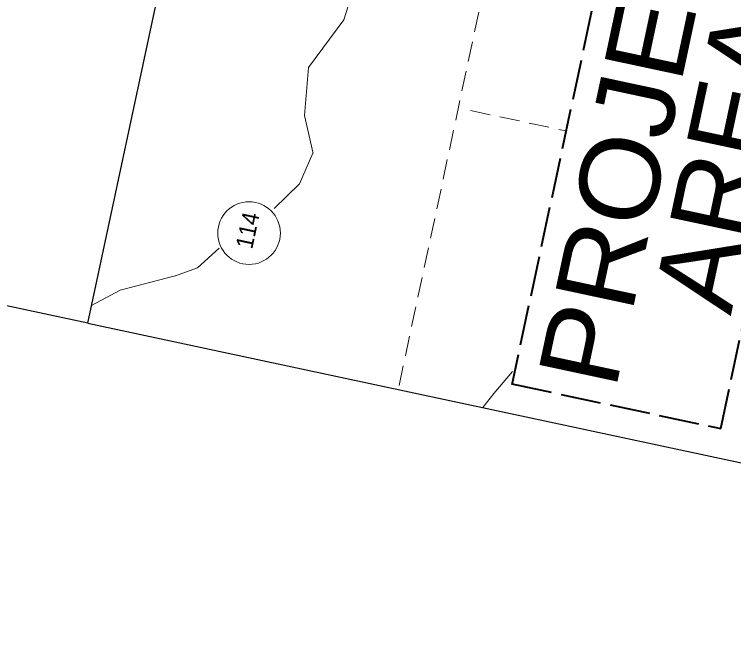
# Model space of a CAD drawing. Extents: x 2363411 to 2369126, y 6976878 to 6988319.
# Drawn here: x 2365656.3 to 2365871.2, y 6976877.7 to 6977067.2 of the extents above; entities that cross this region are included whole.
import ezdxf

# ---------------------------------------------------------------- set-up
doc = ezdxf.new("R2010")
doc.units = 0
doc.header["$LTSCALE"] = 2
doc.linetypes.add('LONG_DASHED', pattern=[7.5, 6, -1.5])
doc.linetypes.add('MEDIUM_DASHED', pattern=[4.5, 3, -1.5])
doc.layers.add('62', color=7, linetype='Continuous', lineweight=13)
doc.layers.add('63', color=7, linetype='Continuous', lineweight=13)

msp = doc.modelspace()

# ---------------------------------------------------------------- linework, layer by layer
at = {"layer": '62', "lineweight": 25}
msp.add_line((2365678.211, 6976974.92), (2365772.152, 6977414.588), dxfattribs=at)
at = {"layer": '62', "linetype": 'MEDIUM_DASHED'}
for p, q in [((2365864.629, 6977393.47), (2365770.962, 6976955.102)), ((2365792.552, 6977038.481), (2365821.113, 6977032.378))]:
    msp.add_line(p, q, dxfattribs=at)
at = {"layer": '62'}
for p, q in [((2365745.482, 6977025.71), (2365741.426, 6977016.523)), ((2365741.426, 6977016.523), (2365733.932, 6977009.242)), ((2365710.989, 6976991.456), (2365717.459, 6976997.299)), ((2365704.102, 6976988.947), (2365710.989, 6976991.456)), ((2365799.574, 6976953.962), (2365805.114, 6976960.509)), ((2365796.248, 6976949.699), (2365799.574, 6976953.962))]:
    msp.add_line(p, q, dxfattribs=at)
at = {"layer": '62', "lineweight": 25}
for points in [[(2365678.211, 6976974.92), (2365561.054, 6976999.954), (2365654.924, 6977439.292), (2365772.152, 6977414.588)], [(2365678.211, 6976974.92), (2366133.213, 6976877.7), (2366227.156, 6977317.368), (2365772.152, 6977414.588)]]:
    msp.add_lwpolyline(points, dxfattribs=at)
at = {"layer": '62'}
for points in [[(2365745.602, 6977025.615), (2365742.995, 6977037.011), (2365744.177, 6977051.369), (2365754.758, 6977065.562), (2365757.967, 6977076.059), (2365767.656, 6977087.91), (2365774.215, 6977096.102), (2365778.852, 6977103.376), (2365783.338, 6977114.034), (2365786.122, 6977122.873), (2365789.101, 6977134.663), (2365791.544, 6977148.682), (2365797.575, 6977165.918), (2365800.831, 6977177.279), (2365805.2, 6977190.083), (2365814.728, 6977203.211), (2365824.115, 6977215.605), (2365833.318, 6977226.804), (2365847.376, 6977238.756), (2365856.409, 6977246.882), (2365866.274, 6977257.086), (2365874.425, 6977262.384)], [(2365679.344, 6976980.224), (2365687.88, 6976984.754), (2365704.316, 6976989.086)]]:
    msp.add_lwpolyline(points, dxfattribs=at)
at = {"layer": '62', "linetype": 'LONG_DASHED', "lineweight": 40}
msp.add_lwpolyline([(2365804.964, 6976956.79), (2365867.37, 6976943.454), (2365903.697, 6977113.468), (2365841.291, 6977126.802), (2365804.897, 6976956.481)], dxfattribs=at)
at = {"layer": '62'}
msp.add_circle((2365726.392, 6977001.845), 9.364, dxfattribs=at)
at = {"layer": '63', "lineweight": 25}
msp.add_line((2365678.211, 6976974.92), (2365772.152, 6977414.588), dxfattribs=at)
at = {"layer": '63', "linetype": 'MEDIUM_DASHED'}
for p, q in [((2365864.629, 6977393.47), (2365770.962, 6976955.102)), ((2365792.552, 6977038.481), (2365821.113, 6977032.378))]:
    msp.add_line(p, q, dxfattribs=at)
at = {"layer": '63'}
for p, q in [((2365745.482, 6977025.71), (2365741.426, 6977016.523)), ((2365741.426, 6977016.523), (2365733.932, 6977009.242)), ((2365710.989, 6976991.456), (2365717.459, 6976997.299)), ((2365704.102, 6976988.947), (2365710.989, 6976991.456)), ((2365799.574, 6976953.962), (2365805.114, 6976960.509)), ((2365796.248, 6976949.699), (2365799.574, 6976953.962))]:
    msp.add_line(p, q, dxfattribs=at)
at = {"layer": '63', "lineweight": 25}
for points in [[(2365678.211, 6976974.92), (2365561.054, 6976999.954), (2365654.924, 6977439.292), (2365772.152, 6977414.588)], [(2365678.211, 6976974.92), (2366133.213, 6976877.7), (2366227.156, 6977317.368), (2365772.152, 6977414.588)]]:
    msp.add_lwpolyline(points, dxfattribs=at)
at = {"layer": '63'}
for points in [[(2365745.602, 6977025.615), (2365742.995, 6977037.011), (2365744.177, 6977051.369), (2365754.758, 6977065.562), (2365757.967, 6977076.059), (2365767.656, 6977087.91), (2365774.215, 6977096.102), (2365778.852, 6977103.376), (2365783.338, 6977114.034), (2365786.122, 6977122.873), (2365789.101, 6977134.663), (2365791.544, 6977148.682), (2365797.575, 6977165.918), (2365800.831, 6977177.279), (2365805.2, 6977190.083), (2365814.728, 6977203.211), (2365824.115, 6977215.605), (2365833.318, 6977226.804), (2365847.376, 6977238.756), (2365856.409, 6977246.882), (2365866.274, 6977257.086), (2365874.425, 6977262.384)], [(2365679.344, 6976980.224), (2365687.88, 6976984.754), (2365704.316, 6976989.086)]]:
    msp.add_lwpolyline(points, dxfattribs=at)
at = {"layer": '63', "linetype": 'LONG_DASHED', "lineweight": 40}
msp.add_lwpolyline([(2365804.964, 6976956.79), (2365867.37, 6976943.454), (2365903.697, 6977113.468), (2365841.291, 6977126.802), (2365804.897, 6976956.481)], dxfattribs=at)
at = {"layer": '63'}
msp.add_circle((2365726.392, 6977001.845), 9.364, dxfattribs=at)

# ---------------------------------------------------------------- texts
at = {"layer": '62'}
for s, height, width, p in [('PROJECT', 23.83, 1.1, (2365835.896, 6976954.668)), ('AREA', 23.83, 1.05, (2365870.348, 6976976.988)), ('114', 5.099, 0.95, (2365727.326, 6976996.849))]:
    msp.add_text(s, height=height, rotation=77.939, dxfattribs=dict(at, width=width)).set_placement(p)
at = {"layer": '63'}
for s, height, width, p in [('PROJECT', 23.83, 1.1, (2365835.896, 6976954.668)), ('AREA', 23.83, 1.05, (2365870.348, 6976976.988)), ('114', 5.099, 0.95, (2365727.326, 6976996.849))]:
    msp.add_text(s, height=height, rotation=77.939, dxfattribs=dict(at, width=width)).set_placement(p)

doc.saveas('drawing.dxf')
